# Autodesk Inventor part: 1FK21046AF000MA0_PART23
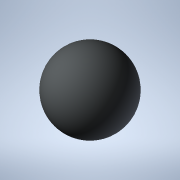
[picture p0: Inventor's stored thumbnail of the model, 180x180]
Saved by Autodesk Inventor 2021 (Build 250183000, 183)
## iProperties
Created: 2025-04
Part Number: 1FK21046AF000MA0_PART23
Material: Generic
Catalog Web Link: www.3dfindit.com
Description: -Servo synchronous motor
Document SubType Name: Modeling
Designer: psAdmin
Mass: 0.137258 g
Surface Area: 1.2868 cm^2
Volume: 0.137258 cm^3
Density: 1 g/cm^3
Appearance: PSOLRGB-212-217-219
Category: PARTsolutions
Title: 1FK21046AF000MA0_PART23
Author: Cadenas PARTsolutions
Comments: Servo synchronous motor
Sending System: PARTsolutions
Preprocessor: ST-DEVELOPER v19.3
PSOL_IDENT_0: {$CADENAS_DATA/23d-libs/siemens_ag/_cat_/1c/1f/1fk21046af000ma0.prj},216 {VTYP=3D},{NB=1FK21046AF000
PSOL_IDENT_1: MA0_PART23},{LINA=1FK21046AF000MA0_PART23},{NN=1FK21046AF000MA0_PART23},{NOPRJ=TRUE},{DATE=19.08.202
PSOL_IDENT_2: 5 14:00:28},{GEOMDATE=30.07.2025 02:02:08},{VERSION=},{LINEID=10},{WBVAR=},{WBNUMERIC=}  {NB=1FK2104
PSOL_IDENT_3: 6AF000MA0_PART23},{LINA=1FK21046AF000MA0_PART23},{KT=DUMMY},{PREVIEW=../../../_pool_/cb/72/p_d211_xx
PSOL_IDENT_4: _00434j.png},{DESCSHORT=SIMOTICS S-1FK2 HD, SINAMICS S210 3AC 400V-480V, 3.2 Nm, 3000 rpm},{DESCLONG=
PSOL_IDENT_5: SIMOTICS S-1FK2 HD servo motor M0=3.2 Nm; PN = 1 kW at nN=3000 rpm (380-480 V); PN = 0.5 kW at nN=15
PSOL_IDENT_6: 00 rpm (200-240 V); degree of protection IP64; cylindrical shaft D19x40mm; absolute encoder 22-bit +
PSOL_IDENT_7: 12-bit multiturn (encoder AM22DQC); with OCC interface; plug size M17, rotatable; SIMOTICS S-1FK2 s
PSOL_IDENT_8: ervomotorfor a wide range of uses in industrial environments. SIMOTICS S‑1FK2 servomotors are compac
PSOL_IDENT_9: t synchronous motors with a high dynamic performance that set themselves apart as a result of their
PSOL_IDENT_10: high power density, degree of protection and overload capability. The motors are available in two va
PSOL_IDENT_11: riants: as High Dynamic variant (highest dynamic performance as a result of the low intrinsic moment
PSOL_IDENT_12: of inertia for applications demanding a high dynamic performance with low moved masses) - and as Co
PSOL_IDENT_13: mpact variant (precise and stable closed-loop control for medium up to large moved masses as a resul
PSOL_IDENT_14: t of a medium intrinsic moment of inertia). SIMOTICSS‑1FK2 servomotors fully exploit their strengths
PSOL_IDENT_15: in a system with the SINAMICSS210 frequency converter and simple connection using the one cable con
PSOL_IDENT_16: nection (OCC). Advantages include the short control and positioning times, fast and precise correcti
PSOL_IDENT_17: on of disturbing quantities as well as stable control with a high dynamic performance. The servo mot
PSOL_IDENT_18: ors can be configured to address a wide range of requirements. For example with and without holding
PSOL_IDENT_19: brake, IP64 or IP65 degree of protection, singleturn or multiturn absolute encoders - to name just a
PSOL_IDENT_20: few. Further, the servomotors are available in different shaft heights extending from 20 to 100. A
PSOL_IDENT_21: shaft sealing ring is available to achieve an IP65 degree of protection and for subsequent mounting
PSOL_IDENT_22: at the motor or as spare part. SIMOTICS - the optimum motor for each and every motion control applic
PSOL_IDENT_23: ation.},{INTNO=195125049666},{SUPPLIERALTNO=1FK2104-6AF00-0MA0},{MANUID=1FK21046AF000MA0},{MANUNAME=
PSOL_IDENT_24: Siemens},{MANUTYPEDESC=Synchronous motor 1FK2-HD 3.2 NM},{AAU732=SIMOTICS},{AAO057=S-1FK2},{AAU734=S
PSOL_IDENT_25: IMOTICS S-1FK2 HD servo motor M0=3.2 Nm; PN = 1 kW at nN=3000 rpm (380-480 V); PN = 0.5 kW at nN=150
PSOL_IDENT_26: 0 rpm (200-240 V); degree of protection IP64; cylindrical shaft D19x40mm; absolute encoder 22-bit +
PSOL_IDENT_27: 12-bit multiturn (encoder AM22DQC); with OCC interface; plug size M17, rotatable;},{AAW338=Synchrono
PSOL_IDENT_28: us motor 1FK2-HD 3.2 NM},{AAO742=SIMOTICS},{AAO663=4042948694374},{NOCUPEROU=1},{PRICEQUANTITY=1},{Q
PSOL_IDENT_29: UANTITYMIN=1},{QUANTITYINT=1},{CTN=85015220},{COO=DE},{AAO676=1FK2104-6AF00-0MA0},{AAO677=Siemens AG
PSOL_IDENT_30: },{ORDERUNIT=C62},{CONTENTUNIT=C62}
NB: 1FK21046AF000MA0_PART23
NT: Servo synchronous motor
NBSYN: $MANUID._PART23
LINA: 1FK21046AF000MA0_PART23
CATALOG: SIEMENS
PREVIEW: ../../../_pool_/cb/72/p_d211_xx_00434j.png
DESCSHORT: SIMOTICS S-1FK2 HD, SINAMICS S210 3AC 400V-480V, 3.2 Nm, 3000 rpm
DESCLONG: SIMOTICS S-1FK2 HD servo motor M0=3.2 Nm; PN = 1 kW at nN=3000 rpm (380-480 V); PN = 0.5 kW at nN=1500 rpm (200-240 V); degree of protection IP64; cylindrical s
INTNO: 195125049666
SUPPLIERALTNO: 1FK2104-6AF00-0MA0
MANUID: 1FK21046AF000MA0
MANUNAME: Siemens
MANUTYPEDESC: Synchronous motor 1FK2-HD 3.2 NM
AAU732: SIMOTICS
AAO057: S-1FK2
AAU734: SIMOTICS S-1FK2 HD servo motor M0=3.2 Nm; PN = 1 kW at nN=3000 rpm (380-480 V); PN = 0.5 kW at nN=1500 rpm (200-240 V); degree of protection IP64; cylindrical s
AAW338: Synchronous motor 1FK2-HD 3.2 NM
AAO742: SIMOTICS
AAO663: 4042948694374.0
NOCUPEROU: 1
PRICEQUANTITY: 1
QUANTITYMIN: 1
QUANTITYINT: 1
CTN: 85015220
COO: DE
ARTICLENO: 1FK21046AF000MA0_PART23
BOMINFO: 1FK21046AF000MA0_PART23
CREATOR: CADENAS GmbH
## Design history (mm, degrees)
feature "2025_04_17_15_39_11_0412"
body "Solid1"
